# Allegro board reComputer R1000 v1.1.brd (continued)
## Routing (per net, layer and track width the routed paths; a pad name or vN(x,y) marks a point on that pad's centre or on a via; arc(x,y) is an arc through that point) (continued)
HDMI0_TX1_P1: length 11.6
  BOTTOM w0.095: L20.1 108.32,50.38 U8.7 U8.4 108.32,48.6 108.21,48.49 108.21,48 108.01,47.81 108.01,47.67 108.25,47.43 108.25,47.3 108.11,47.16 107.98,47.16 107.74,47.4 107.6,47.4 106.76,46.56 106.76,45.22 107.69,44.29 108.84,44.29 109.17,43.96 J9.4
HDMI0_TX2_N: length 72.7
  TOP w0.095: v1(59.75,37.64) 59.86,37.75 59.86,38.13 59.8,38.19 J5.172
  LYR3 w0.102: v1(59.75,56.2) 59.75,55.98 59.85,55.88 59.85,37.96 59.75,37.86 v1(59.75,37.64)
  LYR6 w0.102: v1(59.75,56.2) 59.75,55.98 59.85,55.88 59.85,55.61 60.13,55.33 61.38,55.33 61.72,54.98 100.21,54.98 103.25,51.93 104.88,51.93 105.01,51.8 105.36,51.8 105.49,51.93 105.84,51.93 105.97,51.8 106.33,51.8 106.45,51.93 106.81,51.93 106.94,51.8 107.29,51.8 107.42,51.93 107.77,51.93 107.9,51.8 108.26,51.8 108.38,51.93 108.89,51.93 109.42,51.4 109.42,51.26 109.31,51.16 v1(109.31,50.94)
HDMI0_TX2_N1: length 8.9
  BOTTOM w0.095: L19.4 109.32,50.38 U8.9 U8.2 109.32,48.53 109.43,48.42 109.43,48.17 111.28,46.32 111.28,44.91 110.18,43.81 110.18,43.38 J9.3
HDMI0_TX2_P: length 72.7
  TOP w0.095: J5.170 60.2,38.19 60.14,38.13 60.14,37.76 v1(60.26,37.64) ; 109.81,50.93 v1(109.82,50.94)
  LYR3 w0.102: v1(60.26,37.64) 60.26,37.86 60.16,37.96 60.16,55.88 60.26,55.98 v1(60.26,56.2)
  LYR6 w0.102: v1(60.26,56.2) 60.26,55.98 60.16,55.88 60.16,55.73 60.26,55.63 61.5,55.63 61.85,55.28 62.21,55.28 62.33,55.41 62.69,55.41 62.82,55.28 63.78,55.28 63.91,55.41 64.26,55.41 64.39,55.28 65.1,55.28 65.23,55.41 65.59,55.41 65.71,55.28 66.12,55.28 66.25,55.41 66.6,55.41 66.73,55.28 100.33,55.28 103.38,52.23 109.01,52.23 109.72,51.53 109.72,51.26 109.82,51.16 v1(109.82,50.94)
HDMI0_TX2_P1: length 10.8
  BOTTOM w0.095: J9.1 110.46,43.38 110.46,43.7 110.88,44.11 111.01,44.11 111.18,43.94 111.32,43.94 111.45,44.07 111.45,44.21 111.28,44.38 111.28,44.51 111.56,44.79 111.56,44.94 111.65,45.04 111.9,45.04 111.99,45.13 111.99,45.32 111.9,45.42 111.65,45.42 111.56,45.51 111.56,45.71 111.65,45.8 111.9,45.8 111.99,45.9 111.99,46.09 111.9,46.18 111.65,46.18 111.56,46.28 111.56,46.43 109.71,48.29 109.71,48.43 109.82,48.54 U8.1 U8.10 109.82,50.38 L19.1
IO_BUZZER_EN: length 6.9
  TOP w0.121: v1(27.64,72.76) 28.15,73.27 29.44,73.27 29.68,73.03 U12.15
  LYR6 w0.121: v1(25.1,72.66) 25.35,72.91 27.49,72.91 v1(27.64,72.76)
  BOTTOM w0.121: R39.1 24.62,73.14 v1(25.1,72.66)
LORA_3V3: length 7.8
  TOP w0.305: v1(71.25,36.59) 71.09,36.42 C112.2
  BOTTOM w0.305: C114.2 44.22,35.34 v1(44.25,35.32) J14.52 ; v1(71.25,36.59) 71.25,35.32 J14.2 ; J14.24 v1(59.24,34.03)
  vias: v1(41.76,26.68) v1(41.76,26.2) v1(42.19,26.71) v1(42.19,26.22) v1(50.75,24.12) v1(50.75,23.66) v1(51.21,24.12) v1(51.21,23.66) v1(59.36,33.59)
LORAWAN_SX1262_CS: length 74.4
  TOP w0.121: U12.1 28.18,67.15 v1(28.17,67.14)
  LYR3 w0.121: v1(57.84,29.12) 57.84,32.35 57.56,32.63 57,32.63 56.54,33.08 56.09,33.08 55.76,33.41 55.76,36.83 56.61,37.69 56.61,51.64 58.5,53.53 58.5,60.34 57.18,61.66 v1(57.18,66.46)
  LYR6 w0.121: v1(57.18,66.46) 56.76,66.87 55.51,66.87 54.75,67.63 43.59,67.63 43.11,67.14 v1(28.17,67.14)
  BOTTOM w0.121: J14.25 58.84,28.22 58.64,28.42 58.1,28.42 57.84,28.69 v1(57.84,29.12)
LORAWAN_SX1262_RST: length 74.5
  TOP w0.121: U12.2 28.68,66.97 27.61,65.9 v1(27.61,61.91)
  LYR3 w0.121: v1(68.2,59.91) 68.23,59.91 68.35,59.78 68.35,40.83 68.58,40.6 68.58,37.03 v1(68.04,36.49)
  LYR6 w0.121: v1(68.2,59.91) 68.13,59.98 66.91,59.98 64.49,62.39 45.27,62.39 44.2,61.33 28.2,61.33 v1(27.61,61.91)
  BOTTOM w0.121: J14.10 v1(68.04,36.49)
LORAWAN_SX1302_RST: length 78.2
  TOP w0.121: v1(62.61,36.71) 60.61,34.71 60.61,33.67 59.99,33.05 R110.2 ; v1(28.04,62.52) 28.04,65.97 29.18,67.1 U12.3
  LYR3 w0.121: v1(62.61,36.71) 62.94,36.71 65.51,39.28 65.51,52.87 65.05,53.33 65.05,53.83 65.48,54.27 v1(65.48,63.41)
  LYR6 w0.121: v1(28.04,62.52) 28.19,62.38 31.49,62.38 31.96,61.91 43.94,61.91 45.01,62.98 62.99,62.98 63.43,63.41 v1(65.48,63.41)
LTE_RESET: length 94
  TOP w0.121: v1(28.35,61.94) 28.5,62.09 28.5,65.96 29.68,67.14 U12.4
  LYR3 w0.121: v1(94.39,39.91) 94.57,40.09 94.57,42.07 89.82,46.82 v1(89.82,60.51)
  LYR6 w0.121: v1(28.35,61.94) 31.27,61.94 31.54,61.66 44.1,61.66 45.17,62.73 64.56,62.73 66.98,60.31 70.11,60.31 70.56,59.85 74.2,59.85 74.93,60.59 89.74,60.59 v1(89.82,60.51)
  BOTTOM w0.121: R109.2 v1(94.39,39.91)
NEXTRST: length 43.2
  TOP w0.121: v1(60.86,36.66) 59.79,35.6 58.47,35.6 58.24,35.37 R46.1 ; J4.100 v1(54.2,72.08)
  LYR3 w0.121: v1(60.86,36.66) 60.86,43.24 61.78,44.16 61.78,58.69 58.55,61.91 58.55,66.38 54.2,70.73 v1(54.2,72.08)
NLNKA_LED: length 24.8
  TOP w0.121: R83.1 v1(44.1,23.51) ; U4.21 52.34,37.41 50.9,38.85 46.08,38.85 45.37,38.14 45.37,36.87 v1(45.65,36.59)
  LYR3 w0.121: v1(44.1,23.51) 44.1,25.36 46.08,27.34 46.08,35.88 45.65,36.31 v1(45.65,36.59)
NPIBOOT: length 95.2
  TOP w0.121: J4.93 55.4,74.79 54.99,74.38 50.01,74.38 45.79,70.15 39.77,70.15 v1(38.81,71.11)
  LYR3 w0.121: v1(22.58,75.86) 21.49,74.76 21.49,50.86 13.52,42.89 8.11,42.89 6.71,41.49 6.71,34.61 6.07,33.97 3.02,33.97 J6.2
  LYR6 w0.121: v1(38.81,71.11) 34.06,75.86 29.09,75.86 28.43,75.2 23.24,75.2 v1(22.58,75.86)
NPWR_LED: length 122.3
  TOP w0.121: J4.95 55,74.83 54.83,74.65 49.94,74.65 45.68,70.4 40.31,70.4 v1(39.45,71.26) ; J25.1 10.65,4.82 11.41,5.57 v1(12.42,5.57)
  LYR3 w0.121: v1(12.42,5.57) 12.42,10.39 7.99,14.83 7.99,21.4 6.36,23.03 6.36,26.5 7.71,27.85 7.71,37.66 9.04,38.99 11.93,38.99 12.25,39.31 12.25,40.19 23.27,51.22 23.27,59.3 23.75,59.78 23.75,63.36 23.24,63.87 23.24,68.92 22.91,69.25 22.91,75.25 v1(23.5,75.83)
  LYR6 w0.121: v1(23.5,75.83) 23.88,75.45 28.32,75.45 28.98,76.11 34.44,76.11 39.3,71.26 v1(39.45,71.26)
NSPD_LED: length 22.8
  TOP w0.121: R84.1 v1(45.14,23.5) ; v1(46.23,36.49) 46.23,38.19 46.61,38.57 50.78,38.57 51.84,37.51 U4.22
  LYR3 w0.121: v1(45.14,23.5) 45.08,23.56 45.08,25.99 46.33,27.23 46.33,36.39 v1(46.23,36.49)
PCIE_CLK_N: length 89.8
  TOP w0.095: v1(77.97,56.84) 77.75,56.84 77.64,56.73 77.27,56.73 76.58,56.04 76.58,40.95 75.34,39.7 72.12,39.7 71.86,39.44 71.86,39.09 71.8,39.03 J5.112
  LYR6 w0.102: v1(77.97,56.84) 77.75,56.84 77.65,56.74 66.06,56.74 63.02,59.78 46.59,59.78 45.39,58.58 31.07,58.58 29.32,56.84 16.01,56.84 15.91,56.94 v1(15.69,56.94)
  BOTTOM w0.095: J62.53 14.6,56.94 14.71,56.83 15.36,56.83 15.47,56.94 v1(15.69,56.94)
PCIE_CLK_NREQ: length 90.6
  TOP w0.121: J5.102 75.83,38.75 77.83,40.75 77.83,54.6 78.84,55.61 v1(78.84,64.68)
  BOTTOM w0.121: v1(78.84,64.68) 78.39,64.68 77.57,65.5 59.97,65.5 57.73,63.26 41.22,63.26 36.27,58.31 32.57,58.31 32.04,57.78 23.4,57.78 22.8,57.19 J62.52
PCIE_CLK_P: length 89.7
  TOP w0.095: J5.110 72.2,39.03 72.14,39.09 72.14,39.33 72.24,39.42 73.97,39.42 74.09,39.29 74.45,39.29 74.58,39.42 75.45,39.42 76.86,40.83 76.86,41.19 76.99,41.31 76.99,41.67 76.86,41.79 76.86,54 76.99,54.13 76.99,54.48 76.86,54.61 76.86,54.96 76.99,55.09 76.99,55.45 76.86,55.57 76.86,55.93 77.39,56.45 77.64,56.45 77.75,56.34 v1(77.97,56.34)
  LYR6 w0.102: v1(15.69,56.43) 15.91,56.43 16.01,56.54 29.45,56.54 31.19,58.28 45.52,58.28 46.71,59.47 62.89,59.47 65.93,56.44 77.65,56.44 77.75,56.34 v1(77.97,56.34)
  BOTTOM w0.095: J62.55 14.6,56.44 14.71,56.55 15.36,56.55 15.47,56.43 v1(15.69,56.43)
PCIE_NRST: length 77.5
  TOP w0.121: J5.109 72.2,58.32 69.8,60.72 69.8,65.54 v1(70.16,65.9)
  BOTTOM w0.121: v1(70.16,65.9) 69.73,65.9 69.7,65.87 60,65.87 57.66,63.54 41.15,63.54 36.17,58.56 32.46,58.56 31.93,58.03 22.99,58.03 22.65,57.69 J62.50
PCIE_RX_N: length 89.9
  TOP w0.095: J5.118 70.6,39.03 70.66,39.09 70.66,39.64 71.44,40.41 74.42,40.41 75.54,41.53 75.54,58.87 75.86,59.19 76.23,59.19 76.34,59.31 v1(76.56,59.31)
  LYR6 w0.102: v1(15.56,59.94) 15.78,59.94 15.88,59.84 28.97,59.84 29.64,60.51 44.5,60.51 45.72,61.73 64.11,61.73 66.64,59.21 76.24,59.21 76.34,59.31 v1(76.56,59.31)
  BOTTOM w0.095: v1(15.56,59.94) 15.35,59.94 15.23,59.83 14.71,59.83 14.6,59.94 J62.41
PCIE_RX_P: length 89.9
  TOP w0.095: v1(76.56,58.8) 76.34,58.8 76.23,58.91 75.98,58.91 75.82,58.76 75.82,58.4 75.95,58.28 75.95,57.92 75.82,57.79 75.82,57.44 75.95,57.31 75.95,56.96 75.82,56.83 75.82,44.23 75.95,44.11 75.95,43.75 75.82,43.62 75.82,41.41 75.22,40.82 75.22,40.64 74.97,40.38 74.79,40.38 74.54,40.13 71.55,40.13 70.94,39.52 70.94,39.09 71,39.03 J5.116
  LYR6 w0.102: v1(76.56,58.8) 76.34,58.8 76.24,58.9 66.51,58.9 63.99,61.43 45.85,61.43 44.63,60.21 29.77,60.21 29.1,59.54 15.88,59.54 15.78,59.43 v1(15.56,59.43)
  BOTTOM w0.095: J62.43 14.6,59.44 14.71,59.55 15.23,59.55 15.35,59.43 v1(15.56,59.43)
PCIE_TX_N: length 88.6
  TOP w0.095: v1(74.56,58.43) 74.56,58.21 74.68,58.1 74.68,44.46 74.55,44.33 74.55,43.98 74.68,43.85 74.68,43.5 74.55,43.37 74.55,43.01 74.68,42.89 74.68,41.89 73.94,41.15 70.4,41.15 69.46,40.21 69.46,39.09 69.4,39.03 J5.124
  LYR6 w0.102: v1(16.59,58.44) 16.81,58.44 16.91,58.34 29.04,58.34 30.36,59.65 45.06,59.65 46.15,60.74 63.43,60.74 66.42,57.75 70.56,57.75 70.69,57.87 71.05,57.87 71.17,57.75 71.53,57.75 71.66,57.87 72.01,57.87 72.14,57.75 72.49,57.75 72.62,57.87 72.98,57.87 73.1,57.75 73.46,57.75 73.59,57.87 73.94,57.87 74.07,57.75 74.54,57.75 74.67,57.87 74.67,58.11 74.56,58.21 v1(74.56,58.43)
  BOTTOM w0.095: J62.47 14.6,58.44 14.72,58.33 16.26,58.33 16.37,58.44 v1(16.59,58.44)
PCIE_TX_P: length 88.6
  TOP w0.095: J5.122 69.8,39.03 69.74,39.09 69.74,40.1 69.89,40.25 70.06,40.25 70.3,40.49 70.3,40.65 70.51,40.87 74.06,40.87 74.96,41.77 74.96,58.1 75.07,58.21 v1(75.07,58.43)
  LYR6 w0.102: v1(75.07,58.43) 75.07,58.21 74.97,58.11 74.97,57.74 74.67,57.44 66.3,57.44 63.3,60.44 46.28,60.44 45.19,59.35 30.48,59.35 29.17,58.03 16.91,58.03 16.81,57.93 v1(16.59,57.93)
  BOTTOM w0.095: J62.49 14.6,57.94 14.72,58.05 16.26,58.05 16.37,57.93 v1(16.59,57.93)
PCIE_USIM_PRESE: length 102.9
  TOP w0.121: v1(4.63,45.88) 4.12,45.88 3.9,45.67 J16.K1
  LYR3 w0.121: v1(83.35,34.05) 85.22,35.92 v1(85.22,50.15)
  LYR6 w0.121: v1(4.63,45.88) 5.34,46.6 6.86,46.6 7.67,47.41 55.32,47.41 58.02,50.1 62.33,50.1 62.74,49.69 66.14,49.69 66.58,50.13 85.19,50.13 v1(85.22,50.15)
  BOTTOM w0.121: J15.44 v1(83.35,34.05) ; 4.99,45.88 R114.2 4.63,45.88 v1(4.63,45.88)
PL_NLED: length 126.3
  TOP w0.121: v1(11.56,4.76) 11.65,4.67 J25.2 ; v1(69.32,73.95) 69.8,74.43 J4.21
  LYR3 w0.121: v1(11.56,4.76) 11.56,10.56 7.5,14.62 7.5,21.2 5.86,22.83 5.86,26.71 7.21,28.05 7.21,41.28 8.31,42.39 13.72,42.39 22.71,51.37 22.71,60.06 22.84,60.18 22.84,64.45 v1(22.71,64.58)
  BOTTOM w0.121: v1(22.71,64.58) 22.72,64.57 38.8,64.57 39.9,65.66 44.83,65.66 49.02,69.86 60.84,69.86 61.45,70.47 66.5,70.47 67.92,71.89 67.92,72.73 69.14,73.95 v1(69.32,73.95)
POE_12V:
  vias: v1(35.49,44.21) v1(35.49,43.78) v1(35.47,43.33) v1(35.47,42.85) v1(35.94,44.18) v1(35.94,43.75) v1(35.93,43.31) v1(35.93,42.82) v1(38.71,43.65)
POE_IN_N:
  vias: v1(13.52,8.47) v1(13.97,8.47) v1(14.46,8.47) v1(19.97,17.66) v1(20.4,17.66) v1(20.83,17.66) v1(25.35,19.67) v1(25.35,19.21) v1(25.78,19.65) v1(25.78,19.19) v1(33.56,16.39) v1(33.56,15.89) v1(33.56,15.43) v1(33.56,14.97)
RS485_1_A: length 7.6
  TOP w0.508: v1(88.78,16.06) 88.75,16.06 R129.1 89.36,16.95 R124.2 89.89,16.22 R125.1
  BOTTOM w0.508: v1(88.78,16.06) 89.75,15.09 U24.12
RS485_1_B: length 7
  TOP w0.508: R130.1 90,12.16 R132.1 R129.2 88.48,14.74 v1(88.48,15.44)
  BOTTOM w0.508: U24.13 v1(88.48,15.44)
RS485_2_A: length 8.5
  TOP w0.508: v1(79.28,15.84) 79.28,14.91 R139.1 79.54,12.57 R133.2 81.79,14.24 R135.1
  BOTTOM w0.508: U26.12 78.79,15.35 v1(79.28,15.84)
RS485_2_B: length 7.5
  TOP w0.508: v1(76.94,15.89) 76.94,14.85 R139.2 76.33,14.25 R141.1 77.96,12.28 R140.1
  BOTTOM w0.508: U26.13 77.52,15.3 v1(76.94,15.89)
RS485_3_A: length 10.4
  TOP w0.508: R143.1 74.4,12.28 R142.2 72.82,13.12 72.27,13.68 70.85,13.68 R148.1 69.5,15.12 68.66,15.96 v1(68.07,15.96)
  BOTTOM w0.508: v1(68.07,15.96) 67.77,15.66 U27.12
RS485_3_B: length 8.9
  TOP w0.508: v1(66.68,16.09) R148.2 67.49,14.21 68.1,14.21 69.35,12.96 R149.1 70.98,12.28 R150.1
  BOTTOM w0.508: U27.13 66.5,15.91 v1(66.68,16.09)
RS485_LED1: length 90.9
  TOP w0.121: v1(15.67,3.09) 15.67,3.92 J25.6 ; U25.3 v1(36.07,62.63)
  LYR3 w0.121: v1(15.67,3.09) 12.22,3.09 11.15,4.15 11.15,10.6 7.24,14.52 7.24,21.1 5.62,22.73 5.62,26.81 6.96,28.16 6.96,41.38 8.21,42.63 13.62,42.63 22.41,51.42 22.41,60.41 22.43,60.44 v1(22.43,61.02)
  BOTTOM w0.121: v1(22.43,61.02) 22.46,61 34.47,61 36.07,62.6 v1(36.07,62.63)
RS485_LED2: length 89.1
  TOP w0.121: J25.7 16.64,3.93 v1(16.64,3.01) ; U25.6 v1(34.12,62.35)
  LYR3 w0.121: v1(16.64,3.01) 16.13,3.52 12.5,3.52 11.97,4.05 11.97,10.5 7.74,14.72 7.74,21.3 6.11,22.93 6.11,26.6 7.46,27.95 7.46,41.18 8.42,42.14 13.83,42.14 22.99,51.3 22.99,59.65 23.29,59.96 v1(23.29,61.45)
  BOTTOM w0.121: v1(34.12,62.35) 33.23,61.45 v1(23.29,61.45)
RS485_LED3: length 83
  TOP w0.121: v1(33.11,58.98) 33.47,58.62 U25.8 ; J25.8 17.65,3.01 v1(17.63,2.98)
  LYR3 w0.121: v1(17.63,2.98) 16.84,3.77 13.19,3.77 12.84,4.12 12.84,10.33 8.24,14.93 8.24,21.5 6.61,23.14 6.61,26.4 7.95,27.74 7.95,37.56 9.14,38.75 12.04,38.75 12.49,39.2 12.49,40.09 23.68,51.27 v1(23.68,58.74)
  BOTTOM w0.121: v1(23.68,58.74) 24.14,58.28 31.8,58.28 32.5,58.98 v1(33.11,58.98)
RS485_POWER_EN: length 93.3
  TOP w0.121: U12.14 30.18,73.47 v1(30.2,73.49) ; R122.1 v1(74.37,24.17)
  LYR3 w0.121: v1(30.71,67.88) 29.92,68.67 29.92,73.21 v1(30.2,73.49) ; v1(74.37,24.17) 75.14,24.93 75.14,27.65 75.75,28.26 75.75,44.44 69.65,50.53 69.65,66.1 v1(70.28,66.74)
  LYR6 w0.121: v1(70.28,66.74) 70.23,66.74 69.83,67.14 55.6,67.14 54.87,67.88 v1(30.71,67.88)
RTC_INT: length 6.5
  TOP w0.121: U16.3 v1(11.53,69.76)
  BOTTOM w0.121: v1(11.53,69.76) 10.72,70.57 10.72,73.22 R104.2 12.21,73.76 C109.1
RUN_PG: length 98.2
  TOP w0.121: v1(48.9,71.92) 49.15,71.67 55.3,71.67 55.8,72.17 J4.92
  LYR3 w0.121: v1(48.9,71.92) 48.9,71.72 43.61,66.43 43.61,53.28 34.67,44.33 34.67,31.41 39.21,26.87 39.21,24.99 39.7,24.5 39.7,22.59 38.36,21.25 v1(37.82,21.25)
  LYR6 w0.121: v1(37.82,21.25) 35.84,21.25 34.75,20.15 31.42,20.15 29.75,18.48 18.77,18.48 17.1,16.81 10.97,16.81 v1(9.83,17.94)
  BOTTOM w0.121: v1(9.83,17.94) 9.83,17.94 R36.2
SD_VDD_OVERRIDE: length 2.8
  TOP w0.121: J4.73 59.4,78.02 R26.1
TPM_RST: length 70.5
  TOP w0.121: v1(26.08,61.94) 26.08,61.92 26.62,61.38 28.48,61.38 28.86,61.76 28.86,65.72 30.18,67.04 U12.5
  LYR3 w0.121: v1(17.1,17.56) 17.1,17.59 15.01,19.67 13.06,19.67 12.58,20.15 12.58,23.26 12.97,23.66 12.97,26.07 10,29.04 10,37.09 10.41,37.5 12.67,37.5 22.3,47.13 25.33,47.13 26.08,47.89 v1(26.08,61.94)
  BOTTOM w0.121: J13.3 v1(17.1,17.56)
TRCT: length 32.9
  TOP w0.305: v1(47.52,22.1) C88.1 47.09,22.11 R82.2
  BOTTOM w0.305: 50.08,5.79 48.56,4.27 J10.9 ; 50.08,5.79 50.45,5.79 ; 50.08,5.79 50.27,5.98 ; 50.27,5.98 J10.5 49,16.79 J10.4 49,21.43 48.32,22.1 v1(47.52,22.1) ; 50.27,5.98 50.45,5.79 ; 50.45,5.79 J10.12
UART2_RXD: length 101.5
  TOP w0.121: R126.2 v1(77.41,18.61) ; v1(37.42,62.6) 37.37,62.64 U25.1
  LYR3 w0.121: v1(74.93,63.36) 74.2,62.63 74.2,48.1 78.08,44.22 78.08,19.29 v1(77.41,18.61)
  LYR6 w0.121: v1(37.42,62.6) 37.61,62.41 43.65,62.41 44.72,63.47 62.63,63.47 63.23,64.07 74.22,64.07 v1(74.93,63.36) ; v1(86.67,22.77) 86.72,22.72 86.72,19.87 85.46,18.61 v1(77.41,18.61)
  BOTTOM w0.121: v1(86.67,22.77) 86.67,22.9 87.21,23.44 U24.3
UART2_TXD: length 109.2
  TOP w0.121: R128.2 v1(74.51,18.61) ; U25.2 36.72,62.38 v1(36.76,62.34)
  LYR3 w0.121: v1(73.79,63.41) 73.79,63.36 73.92,63.23 73.92,47.89 77.81,44 77.81,20.47 77.35,20 75.29,20 74.51,19.22 v1(74.51,18.61)
  LYR6 w0.121: v1(91.04,22.85) 85.96,17.77 75.36,17.77 v1(74.51,18.61) ; v1(73.79,63.41) 73.38,63.82 63.32,63.82 62.73,63.23 44.85,63.23 43.79,62.16 36.94,62.16 v1(36.76,62.34)
  BOTTOM w0.121: v1(91.04,22.85) 91.02,22.86 U24.6
UART_3V3: length 92.3
  TOP w0.254: U15.1 35.09,55.19 34.8,55.49 34.8,56.48 v1(34.72,56.55) 34.8,56.63 C100.2 ; v1(33.38,53.02) 33.64,53.28 R98.1
  LYR3 w0.381: v1(59.79,7.05) 59.34,7.5 59.34,13.52 57.61,15.25 57.61,17.49 54.82,20.28 v1(54.82,21.35) ; v1(34.72,56.55) 33.78,55.61 33.78,53.73 33.38,53.33 v1(33.38,53.02) 33.82,52.58 33.82,51.82 33.33,51.32 28.65,51.32 26.67,49.34 26.67,47.71 25.89,46.93 25.89,38.65 28.32,36.21 28.32,30.49 v1(29.12,29.69) 32.9,25.92 v1(32.9,23.79)
  LYR6 w0.381: v1(32.9,23.79) 32.94,23.74 37.67,23.74 38.51,22.9 48.57,22.9 50.06,21.4 54.76,21.4 v1(54.82,21.35)
  BOTTOM w0.381: v1(59.79,7.05) 59.92,6.92 TP21.1 ; D24.1 29.14,29.68 v1(29.12,29.69)
USB1_RST: length 65.6
  TOP w0.121: v1(76.63,68.52) 77.27,69.15 v1(77.27,72.76) ; U4.12 55.51,33.98 56.01,34.48 C55.1 56.74,34.75 56.92,34.94 57.6,34.94 58.22,34.32 R46.2 ; R46.2 58.51,34.32 58.78,34.58 58.78,35.01 59.01,35.24 60.28,35.24 61.29,36.26 v1(61.29,37.17) ; R46.2 R44.2
  LYR3 w0.121: v1(58.8,68.34) 58.8,62.19 62.05,58.94 62.05,43.9 61.19,43.04 61.19,37.27 v1(61.29,37.17)
  BOTTOM w0.121: R64.1 v1(77.27,72.76) ; v1(76.63,68.52) 58.92,68.52 58.8,68.4 v1(58.8,68.34)
USB2_RST: length 17.4
  TOP w0.121: U5.26 v1(94.87,67.95)
  BOTTOM w0.121: v1(94.87,67.95) 94.5,67.95 93.65,68.8 88.16,68.8 C61.1 R52.2 R59.2 82.4,73.1 81.89,73.61 R71.2 81.07,73.61 U6.2
USB2_RST_EN: length 57.9
  TOP w0.121: U12.13 30.96,72.56 31.12,72.4 32.36,72.4 33.05,71.72 v1(33.05,71.26)
  LYR6 w0.121: v1(81.86,72.71) 78.28,72.71 77.14,73.85 70.44,73.85 69.95,74.33 67.67,74.33 66.65,75.35 64.61,75.35 64.39,75.58 54.69,75.58 47.32,68.21 37.29,68.21 34.55,70.95 33.35,70.95 v1(33.05,71.26)
  BOTTOM w0.121: R71.1 v1(81.86,72.71)
USB2_VBUS_EN1: length 8.2
  TOP w0.121: R65.1 99.6,73.32 v1(99.49,73.21) 99.49,73.16 99.4,73.07 U5.12 ; v1(101.46,72.41) 101.6,72.27 102.57,72.27 102.81,72.52 R75.2 103.29,73.38 103.67,73.76 U7.1
  LYR6 w0.121: v1(99.49,73.21) 99.62,73.34 100.54,73.34 v1(101.46,72.41)
USB2_VBUS_EN2: length 11.5
  TOP w0.121: R66.1 97.26,73.19 v1(97.23,73.16) 97.4,73 U5.16 ; U7.4 103.68,69.95 v1(103.66,69.96) 103.65,69.95 R74.2
  LYR6 w0.121: v1(97.23,73.16) 97.28,73.16 97.89,72.55 100.69,72.55 101.22,72.02 103.33,72.02 103.66,71.69 v1(103.66,69.96)
USB2_VRCURN1: length 9.8
  TOP w0.121: U7.2 105.68,72.49 v1(105.72,72.53) ; U5.13 v1(98.9,73.2) 98.92,73.22 R60.1
  LYR6 w0.121: v1(105.72,72.53) 104.55,73.7 99.34,73.7 98.9,73.26 v1(98.9,73.2)
USB2_VRCURN2: length 14.8
  TOP w0.121: R61.1 96.59,73.22 v1(96.6,73.21) 96.9,72.91 U5.17 ; v1(105.74,71.21) 105.69,71.21 105.68,71.22 U7.3
  LYR6 w0.121: v1(105.74,71.21) 106.2,71.67 106.2,73.11 105.31,74 97.39,74 v1(96.6,73.21)
USB_0M: length 15.5
  TOP w0.114: v1(51.34,28.8) 51.45,28.69 51.45,28.43 51.34,28.32 U4.58 ; U3.7 v1(58.72,29.59)
  LYR3 w0.127: v1(58.72,29.59) 60,29.59 60.12,29.46 60.12,28.76 59.87,28.51 59.75,28.51 59.44,28.21 59.44,28.08 59.16,27.8 54.31,27.8 53.75,28.36 53.75,29.02 52.94,29.83 51.74,29.83 51.44,29.53 51.44,29.15 51.34,29.05 v1(51.34,28.8)
USB_0P: length 15.5
  TOP w0.114: U3.1 v1(61.84,29.59) ; U4.59 51.84,28.32 51.73,28.43 51.73,28.69 v1(51.84,28.8)
  LYR3 w0.127: v1(51.84,28.8) 51.84,29.05 51.74,29.15 51.74,29.4 51.87,29.53 52.81,29.53 53.44,28.89 53.44,28.23 54.18,27.49 59.29,27.49 60.43,28.64 60.43,29.46 60.56,29.59 v1(61.84,29.59)
USB_1M: length 42.8
  TOP w0.114: U3.6 v1(59.09,29.99)
  LYR3 w0.127: v1(35.97,24.25) 37.19,24.25 37.32,24.12 37.32,23.94 36.55,23.18 36.55,21.2 38.74,19.01 41.91,19.01 45.52,22.62 53.57,22.62 54.66,23.71 57.38,23.71 62.63,28.96 62.63,30.22 61.98,30.87 60.56,30.87 60.11,30.42 60.11,30.12 59.98,29.99 v1(59.09,29.99)
  BOTTOM w0.114: U14.6 v1(35.97,24.25)
USB_1P: length 42.8
  TOP w0.114: U3.2 v1(61.44,29.99)
  LYR3 w0.127: v1(61.44,29.99) 60.54,29.99 60.42,30.12 60.42,30.3 60.69,30.57 61.85,30.57 62.32,30.1 62.32,29.08 61.97,28.73 61.79,28.73 61.53,28.47 61.53,28.3 61.28,28.04 61.1,28.04 60.85,27.79 60.85,27.61 60.6,27.36 60.42,27.36 60.17,27.11 60.17,26.93 59.92,26.68 59.74,26.68 59.49,26.43 59.49,26.25 57.25,24.01 56.47,24.01 56.34,24.14 55.98,24.14 55.86,24.01 55.5,24.01 55.37,24.14 55.02,24.14 54.89,24.01 54.54,24.01 53.44,22.92 53.09,22.92 52.96,23.05 52.61,23.05 52.48,22.92 52.12,22.92 52,23.05 51.64,23.05 51.51,22.92 50.5,22.92 50.37,23.05 50.02,23.05 49.89,22.92 49.41,22.92 49.28,23.05 48.92,23.05 48.8,22.92 47.98,22.92 47.86,23.05 47.5,23.05 47.37,22.92 46.46,22.92 46.33,23.05 45.98,23.05 45.85,22.92 45.39,22.92 44.59,22.12 44.41,22.12 44.16,21.87 44.16,21.69 43.59,21.12 43.41,21.12 43.16,20.87 43.16,20.69 42.67,20.2 42.49,20.2 42.24,19.95 42.24,19.77 41.79,19.32 41.05,19.32 40.92,19.44 40.57,19.44 40.44,19.32 39.83,19.32 39.7,19.44 39.35,19.44 39.22,19.32 38.86,19.32 38.42,19.76 38.42,19.94 38.17,20.19 37.99,20.19 36.85,21.33 36.85,22.08 36.98,22.21 36.98,22.57 36.85,22.69 36.85,23.05 37.62,23.82 37.62,24.12 37.75,24.25 v1(38.97,24.25)
  BOTTOM w0.114: U14.2 v1(38.97,24.25)
USB_C_DM: length 40
  TOP w0.114: R530.2 59.24,10.18 59.24,10.35 59.62,10.73 59.62,13.45 57.08,15.99 55.11,15.99 v1(54.99,16.1)
  LYR3 w0.127: v1(54.99,16.1) 55.1,16 55.44,16 55.68,16.24 55.68,16.9 55.55,17.03 55.55,17.39 55.68,17.51 55.68,18.02 54.26,19.44 54.08,19.44 53.83,19.7 53.83,19.87 53.55,20.15 53.37,20.15 53.11,20.41 53.11,20.59 52.43,21.27 52.07,21.27 51.95,21.14 51.59,21.14 51.46,21.27 45.8,21.27 42.29,17.77 37.38,17.77 36.87,18.28 36.87,19.12 36.77,19.22 v1(36.77,19.47)
  BOTTOM w0.114: U14.5 37.06,22.77 37.32,22.52 37.32,22.15 36.88,21.72 36.88,19.8 36.77,19.69 v1(36.77,19.47)
USB_C_DP: length 40
  TOP w0.114: R531.2 58.96,10.19 58.96,10.47 59.34,10.85 59.34,11.2 59.21,11.33 59.21,11.68 59.34,11.81 59.34,12.37 59.21,12.49 59.21,12.85 59.34,12.98 59.34,13.33 57.64,15.03 57.46,15.03 57.21,15.28 57.21,15.46 56.96,15.71 56.07,15.71 55.95,15.58 55.59,15.58 55.46,15.71 55.11,15.71 v1(54.99,15.59)
  LYR3 w0.127: v1(37.28,19.47) 37.28,19.22 37.18,19.12 37.18,18.4 37.51,18.07 42.17,18.07 45.67,21.58 52.56,21.58 55.98,18.15 55.98,16.12 55.56,15.7 55.1,15.7 v1(54.99,15.59)
  BOTTOM w0.114: U14.3 37.86,22.79 37.59,22.52 37.59,22.03 37.16,21.6 37.16,19.8 37.28,19.69 v1(37.28,19.47)
USB_DET: length 22.6
  TOP w0.121: U5.27 v1(94.64,67.45)
  BOTTOM w0.121: v1(94.64,67.45) 94.44,67.45 93.55,68.34 88.01,68.34 84.51,71.84 76.96,71.84 76.57,72.24 R51.2 C60.1
USB_DM: length 24.7
  TOP w0.114: U3.5 59.88,31.31 60.12,31.56 60.12,32.35 v1(60.01,32.46) ; J5.103 73.4,42.42 73.34,42.48 73.34,43.03 73.46,43.15 v1(73.46,43.37)
  LYR3 w0.127: v1(73.46,43.37) 73.46,43.12 73.35,43.02 73.35,41.21 69.5,37.35 69.5,35.72 66.17,32.4 62.13,32.4 61.34,31.61 60.42,31.61 60.11,31.91 60.11,32.36 v1(60.01,32.46)
USB_DP: length 24.6
  TOP w0.114: U3.3 60.68,31.29 60.4,31.56 60.4,32.35 v1(60.52,32.46) ; J5.105 73,42.42 73.06,42.48 73.06,43.03 72.95,43.15 v1(72.95,43.37)
  LYR3 w0.127: v1(72.95,43.37) 72.95,43.12 73.05,43.02 73.05,41.33 72.8,41.08 72.62,41.08 72.37,40.83 72.37,40.65 72.12,40.4 71.94,40.4 71.68,40.15 71.68,39.97 71.43,39.72 71.25,39.72 71,39.47 71,39.29 70.67,38.95 70.49,38.95 70.23,38.7 70.23,38.52 69.19,37.48 69.19,35.85 68.94,35.6 68.76,35.6 68.51,35.35 68.51,35.17 66.73,33.38 66.55,33.38 66.29,33.13 66.29,32.95 66.04,32.7 65.15,32.7 65.03,32.83 64.67,32.83 64.54,32.7 64.19,32.7 64.06,32.83 63.71,32.83 63.58,32.7 62.97,32.7 62.84,32.83 62.49,32.83 62.36,32.7 62,32.7 61.22,31.91 60.54,31.91 60.42,32.04 60.42,32.36 v1(60.52,32.46)
USB_HUB1_DM2: length 83.9
  TOP w0.114: v1(55.68,28.47) 55.67,28.48 U4.1
  LYR3 w0.127: v1(53.62,65.67) 53.72,65.77 54.31,65.77 54.56,65.52 54.56,28.91 54.9,28.57 55.33,28.57 55.43,28.47 v1(55.68,28.47) ; v1(28.58,79.84) 28.9,79.53 28.9,79.02 28.76,78.88 28.76,63.72 29.04,63.44 29.48,63.44 29.58,63.33 v1(29.82,63.33)
  LYR6 w0.127: v1(53.62,65.67) 53.52,65.77 45.72,65.77 43.39,63.44 30.17,63.44 30.07,63.33 v1(29.82,63.33)
  BOTTOM w0.114: J61.6 28.65,80.4 28.63,80.38 28.63,79.89 v1(28.58,79.84)
USB_HUB1_DM3: length 78
  TOP w0.114: v1(92.64,64.19) 92.75,64.07 93.11,64.07 93.23,64.2 93.59,64.2 93.72,64.07 94.07,64.07 94.2,64.2 94.55,64.2 94.68,64.07 95.04,64.07 95.16,64.2 95.52,64.2 95.65,64.07 96.05,64.07 96.18,64.2 96.48,64.2 96.61,64.07 96.91,64.07 97.51,64.67 97.51,65.85 97.4,65.96 U5.30 ; v1(58.99,31.19) 58.88,31.08 58.88,30.55 57.91,29.59 55.69,29.59 55.58,29.48 U4.3
  LYR3 w0.127: v1(67.49,63.36) 67.49,63.11 67.39,63.01 67.39,36.89 64.49,34 62.13,34 61.06,32.93 59.82,32.93 58.89,32 58.89,31.29 v1(58.99,31.19)
  LYR6 w0.127: v1(67.49,63.36) 67.49,63.11 67.39,63.01 67.39,62.7 68.13,61.96 68.48,61.96 68.61,62.09 68.96,62.09 69.09,61.96 70.16,61.96 70.28,62.09 70.64,62.09 70.77,61.96 71.71,61.96 72.6,62.85 72.95,62.85 73.08,62.98 73.43,62.98 73.56,62.85 74.12,62.85 74.25,62.98 74.6,62.98 74.73,62.85 85.58,62.85 86.81,64.08 92.53,64.08 v1(92.64,64.19)
USB_HUB1_DP2: length 83.9
  TOP w0.114: v1(55.68,28.98) U4.2
  LYR3 w0.127: v1(53.62,66.18) 53.72,66.08 54.43,66.08 54.87,65.65 54.87,29.04 55.03,28.88 55.33,28.88 55.43,28.98 v1(55.68,28.98) ; v1(29.52,79.84) 29.2,79.53 29.2,78.89 29.06,78.75 29.06,68.11 29.19,67.98 29.19,67.63 29.06,67.5 29.06,66.92 29.19,66.79 29.19,66.43 29.06,66.31 29.06,65.95 29.19,65.82 29.19,65.47 29.06,65.34 29.06,64.99 29.19,64.86 29.19,64.5 29.06,64.38 29.06,63.85 29.17,63.74 29.48,63.74 29.58,63.84 v1(29.82,63.84)
  LYR6 w0.127: v1(29.82,63.84) 30.07,63.84 30.17,63.74 43.26,63.74 45.6,66.08 53.52,66.08 v1(53.62,66.18)
  BOTTOM w0.114: v1(29.52,79.84) 29.52,80.35 29.92,80.76 J61.4
USB_HUB1_DP3: length 78.1
  TOP w0.114: v1(92.64,63.68) 92.75,63.79 97.03,63.79 97.79,64.55 97.79,65.85 97.9,65.96 U5.31 ; v1(58.49,31.19) 58.6,31.08 58.6,30.67 58.42,30.49 58.26,30.49 58.18,30.57 58.01,30.57 57.85,30.4 57.85,30.24 57.93,30.16 57.93,30 57.8,29.87 55.69,29.87 55.58,29.98 U4.4
  LYR3 w0.127: v1(66.98,63.36) 66.98,63.11 67.08,63.01 67.08,37.02 64.37,34.3 62,34.3 60.94,33.24 59.69,33.24 58.59,32.13 58.59,31.29 v1(58.49,31.19)
  LYR6 w0.127: v1(92.64,63.68) 92.53,63.78 86.93,63.78 85.7,62.55 72.72,62.55 71.83,61.66 68,61.66 67.08,62.57 67.08,63.01 66.98,63.11 v1(66.98,63.36)
USB_HUB2_DM1: length 24.2
  TOP w0.114: v1(102.68,67.45) 102.46,67.45 102.35,67.56 102,67.56 101.89,67.45 U5.1
  LYR6 w0.127: v1(115.13,59.63) 115.23,59.73 115.98,59.73 117.05,60.79 117.05,62.34 115.85,63.54 104.68,63.54 103.99,64.22 103.99,64.99 102.19,66.79 102.19,67.42 102.31,67.55 102.58,67.55 v1(102.68,67.45)
  BOTTOM w0.114: v1(115.13,59.63) 115.11,59.63 115.1,59.62 L4.4
USB_HUB2_DM2: length 24.3
  TOP w0.114: U5.3 v1(101.93,68.45)
  LYR6 w0.127: v1(101.93,68.45) 101.69,68.45 101.59,68.55 101.35,68.55 101.22,68.42 101.22,68.07 101.35,67.94 101.35,67.59 101.22,67.46 101.22,66.1 101.35,65.98 101.35,65.62 101.22,65.49 101.22,65.01 101.47,64.76 101.65,64.76 101.9,64.51 101.9,64.33 102.16,64.08 102.34,64.08 102.59,63.83 102.59,63.65 102.84,63.4 103.02,63.4 103.27,63.14 103.27,62.97 103.52,62.71 103.7,62.71 103.95,62.46 103.95,62.28 104.2,62.03 104.38,62.03 104.64,61.78 104.64,61.6 105.14,61.1 106,61.1 106.12,61.23 106.48,61.23 106.61,61.1 106.96,61.1 107.09,61.23 107.44,61.23 107.57,61.1 107.93,61.1 108.05,61.23 108.41,61.23 108.54,61.1 108.89,61.1 109.02,61.23 109.37,61.23 109.5,61.1 109.86,61.1 109.98,61.23 110.34,61.23 110.47,61.1 110.82,61.1 110.95,61.23 111.31,61.23 111.43,61.1 111.79,61.1 111.91,61.23 112.27,61.23 112.4,61.1 112.75,61.1 112.88,61.23 113.24,61.23 113.36,61.1 114.24,61.1 114.36,61.23 114.36,61.28 114.49,61.4 114.75,61.4 114.87,61.28 114.87,61.23 115,61.1 115.34,61.1 115.65,61.4 115.65,61.84 115.52,61.96 115.27,61.96 v1(115.17,61.86)
  BOTTOM w0.114: L5.2 115.13,61.85 115.14,61.86 v1(115.17,61.86)
USB_HUB2_DM3: length 112.2
  TOP w0.114: v1(102.71,69.95) 102.49,69.95 102.37,70.06 102,70.06 101.89,69.95 U5.6
  LYR3 w0.127: v1(38.37,37.31) 38.47,37.41 38.47,42.57 46.33,50.43 46.33,65.11 v1(46.23,65.21)
  LYR6 w0.127: v1(102.71,69.95) 102.46,69.95 102.36,70.05 100.77,70.05 95.89,65.16 62.87,65.16 62.13,64.43 46.64,64.43 46.33,64.73 46.33,65.11 v1(46.23,65.21)
  BOTTOM w0.114: J14.36 54.44,34.13 54.18,33.87 54.18,33.53 53.81,33.16 46.67,33.16 45.71,34.12 42.89,34.12 40.86,36.16 38.88,36.16 38.48,36.55 38.48,37.2 v1(38.37,37.31)
USB_HUB2_DM4: length 50.2
  TOP w0.114: U5.8 v1(101.93,70.95)
  LYR3 w0.127: v1(86.39,36.59) 86.39,36.83 86.29,36.93 86.29,65.71 86.39,65.81 v1(86.39,66.05)
  LYR6 w0.127: v1(86.39,66.05) 86.39,66.3 86.29,66.4 86.29,66.64 86.41,66.76 87.23,66.76 87.35,66.64 87.71,66.64 87.84,66.76 88.37,66.76 88.5,66.64 88.85,66.64 88.98,66.76 89.33,66.76 89.46,66.64 89.82,66.64 89.94,66.76 90.45,66.76 90.58,66.64 90.93,66.64 91.06,66.76 95.66,66.76 99.95,71.05 101.59,71.05 101.69,70.95 v1(101.93,70.95)
  BOTTOM w0.114: J15.36 86.55,36.47 86.43,36.59 v1(86.39,36.59)
USB_HUB2_DP1: length 24.2
  TOP w0.114: U5.2 101.89,67.95 102,67.84 102.35,67.84 102.46,67.95 v1(102.68,67.95)
  LYR6 w0.127: v1(102.68,67.95) 102.58,67.85 102.19,67.85 101.88,67.55 101.88,66.66 103.69,64.86 103.69,64.1 104.55,63.23 115.73,63.23 116.74,62.22 116.74,60.92 115.86,60.04 115.23,60.04 v1(115.13,60.14)
  BOTTOM w0.114: v1(115.13,60.14) 115.11,60.12 L4.1
USB_HUB2_DP2: length 24.5
  TOP w0.114: U5.4 101.92,68.95 v1(101.93,68.96)
  LYR6 w0.127: v1(115.17,62.37) 115.27,62.27 115.65,62.27 115.95,61.96 115.95,61.28 115.47,60.79 105.01,60.79 100.92,64.89 100.92,68.55 101.22,68.86 101.59,68.86 101.69,68.96 v1(101.93,68.96)
  BOTTOM w0.114: v1(115.17,62.37) 115.15,62.35 L5.3
USB_HUB2_DP3: length 112.1
  TOP w0.114: U5.7 101.89,70.45 102,70.34 102.37,70.34 102.49,70.45 v1(102.71,70.45)
  LYR3 w0.127: v1(38.88,37.31) 38.78,37.41 38.78,42.44 46.64,50.3 46.64,65.11 v1(46.74,65.21)
  LYR6 w0.127: v1(102.71,70.45) 102.46,70.45 102.36,70.35 100.64,70.35 95.76,65.47 62.74,65.47 62,64.73 51.72,64.73 51.59,64.86 51.23,64.86 51.11,64.73 50.75,64.73 50.62,64.86 50.27,64.86 50.14,64.73 49.56,64.73 49.43,64.86 49.08,64.86 48.95,64.73 48.29,64.73 48.16,64.86 47.81,64.86 47.68,64.73 46.76,64.73 46.64,64.86 46.64,65.11 v1(46.74,65.21)
  BOTTOM w0.114: v1(38.88,37.31) 38.76,37.2 38.76,36.66 38.99,36.44 39.35,36.44 39.47,36.56 39.83,36.56 39.96,36.44 40.97,36.44 41.22,36.18 41.4,36.18 41.66,35.93 41.66,35.75 41.91,35.5 42.09,35.5 42.34,35.25 42.34,35.07 43,34.4 45.82,34.4 46.11,34.12 46.29,34.12 46.54,33.87 46.54,33.69 46.79,33.44 47.53,33.44 47.65,33.57 48.01,33.57 48.14,33.44 48.77,33.44 48.9,33.57 49.25,33.57 49.38,33.44 49.96,33.44 50.09,33.57 50.45,33.57 50.57,33.44 51.06,33.44 51.18,33.57 51.54,33.57 51.67,33.44 52.17,33.44 52.3,33.57 52.66,33.57 52.78,33.44 53.7,33.44 53.9,33.64 53.9,33.87 53.64,34.13 J14.38
USB_HUB2_DP4: length 50.2
  TOP w0.114: v1(101.93,71.46) 101.92,71.45 U5.9
  LYR3 w0.127: v1(85.88,36.59) 85.88,36.83 85.98,36.93 85.98,65.71 85.88,65.81 v1(85.88,66.05)
  LYR6 w0.127: v1(85.88,66.05) 85.88,66.3 85.98,66.4 85.98,66.76 86.29,67.07 95.53,67.07 99.82,71.36 101.59,71.36 101.69,71.46 v1(101.93,71.46)
  BOTTOM w0.114: v1(85.88,36.59) 85.86,36.59 85.75,36.47 J15.38
USB_OTG_ID: length 86.7
  TOP w0.121: v1(74.15,42.48) 73.8,42.14 J5.101 ; v1(62.79,28.26) 62.08,28.97 U3.10
  LYR3 w0.121: v1(74.15,42.48) 74.15,37.81 64.59,28.26 v1(62.79,28.26) 61.9,27.37 v1(61.9,24.55)
  LYR6 w0.121: v1(61.9,24.55) 58.04,24.55 55.96,22.47 49.53,22.47 47.88,24.12 41,24.12 39.84,25.28 v1(38.18,25.28) 37.69,25.77 33.25,25.77 31.27,27.75 11.99,27.75 10.44,29.3 v1(10.44,30.39)
  BOTTOM w0.121: R34.2 9.98,32.11 R35.1 9.98,30.64 C37.1 v1(10.44,30.39) ; U14.10 v1(38.18,25.28)
USB_OTG_ID1: length 4.7
  BOTTOM w0.121: 4.68,32.78 J6.5 8.8,32.78 R34.1
USB_TO_UART_DM: length 35.5
  TOP w0.114: U15.8 37.64,52.48 37.53,52.37 37.53,51.48 37.77,51.24 37.93,51.24 38.01,51.32 38.18,51.32 38.34,51.16 38.34,51 38.26,50.92 38.26,50.76 38.71,50.3 39.19,50.3 v1(39.31,50.42)
  LYR3 w0.127: v1(39.31,50.42) 39.21,50.32 38.8,50.32 33.71,45.22 33.71,30.8 37.3,27.2 37.3,24.78 37.18,24.65 v1(36.3,24.65)
  BOTTOM w0.114: U14.7 v1(36.3,24.65)
USB_TO_UART_DP: length 35.5
  TOP w0.114: U15.7 37.14,52.48 37.25,52.37 37.25,51.37 38.6,50.02 39.19,50.02 v1(39.31,49.91)
  LYR3 w0.127: v1(38.61,24.65) 37.73,24.65 37.61,24.78 37.61,27.33 35.38,29.56 35.38,29.74 35.13,29.99 34.95,29.99 34.7,30.24 34.7,30.42 34.44,30.67 34.26,30.67 34.01,30.92 34.01,45.1 34.26,45.35 34.44,45.35 34.7,45.6 34.7,45.78 34.95,46.03 35.13,46.03 35.38,46.28 35.38,46.46 38.93,50.01 39.21,50.01 v1(39.31,49.91)
  BOTTOM w0.114: U14.1 v1(38.61,24.65)
USBA_GND:
  vias: v1(114.35,64.58) v1(114.81,64.6) v1(115.27,64.63)
USBC_DM: length 9.3
  TOP w0.114: J11.A7 63.85,8.71 61.83,8.71 D23.2 60.93,8.72 60.05,8.72 59.92,8.85 59.92,8.92 59.84,9 59.67,9 59.59,8.92 59.59,8.8 59.51,8.72 59.25,8.72 59.13,8.84 59.13,9.28 59.33,9.48 R530.1
  LYR3 w0.076: J11.B7 65.35,8.12 65.35,8.78 65.11,9.03 J11.A7
USBC_DP: length 7.7
  TOP w0.114: R531.1 58.85,9.39 58.85,8.72 59.13,8.44 60.74,8.44 61.18,8 D22.2 61.81,8.44 63.85,8.44 J11.A6 64.46,8.13 J11.B6
USER_LED_B: length 85.7
  TOP w0.121: U12.8 31.91,69.86 v1(31.98,69.79) ; J25.4 v1(13.65,4.79)
  LYR3 w0.121: v1(24.92,67.5) 25.38,67.04 25.38,65.01 24.89,64.52 24.89,51.05 13.51,39.67 13.51,38.75 12.51,37.74 10.23,37.74 9.7,37.22 9.7,28.99 12.72,25.97 12.72,23.76 11.12,22.16 11.12,13.17 11.63,12.66 11.64,12.66 15.14,9.16 15.14,4.63 14.89,4.38 14.06,4.38 v1(13.65,4.79)
  LYR6 w0.121: v1(24.92,67.5) 25.23,67.5 26.96,69.23 31.4,69.23 31.96,69.79 v1(31.98,69.79)
USER_LED_G: length 84.5
  TOP w0.121: v1(13.25,5.21) 12.65,4.61 J25.3 ; v1(31.85,69.13) 31.85,69.23 31.73,69.36 U12.7
  LYR3 w0.121: v1(13.25,5.21) 13.08,5.37 13.08,10.45 12.5,11.04 12.48,11.04 8.49,15.03 8.49,21.61 6.85,23.24 6.85,26.3 8.2,27.64 8.2,37.46 9.24,38.5 12.14,38.5 12.74,39.1 12.74,39.99 24.13,51.38 24.13,66.64 v1(23.8,66.97)
  LYR6 w0.121: v1(31.85,69.13) 31.69,68.96 27.04,68.96 25.05,66.97 v1(23.8,66.97)
USER_LED_R: length 81.7
  TOP w0.121: v1(31.14,66.71) 31.14,68 30.68,68.47 U12.6 ; J25.5 v1(14.65,4.78)
  LYR3 w0.121: v1(14.65,4.78) 14.84,4.96 14.84,9.11 10.87,13.07 10.87,22.26 12.47,23.86 12.47,25.87 9.45,28.89 9.45,37.32 10.12,37.99 12.4,37.99 13.26,38.85 13.26,39.77 24.64,51.15 24.64,65.01 v1(24.95,65.32)
  LYR6 w0.121: v1(31.14,66.71) 26.34,66.71 v1(24.95,65.32)
USIM_1V8: length 51.2
  LYR3 w0.508: v1(5.39,65.32) 5.39,64.17 4.47,63.26 4.47,47.79 5.92,46.34 v1(5.92,45.88)
  LYR6 w0.508: v1(33.25,68.77) 33,68.52 27.31,68.52 24.11,65.32 v1(5.39,65.32)
  BOTTOM w0.305: R114.1 v1(5.92,45.88)
  BOTTOM w0.508: TP29.1 5.94,45.86 v1(5.92,45.88)
USIM_CLK: length 106
  TOP w0.121: J16.C3 29.08,52.12 30.3,53.35 D31.2 31.66,53.14 C123.1 v1(31.27,52.54)
  LYR3 w0.121: v1(91.01,61.9) 91.08,61.83 91.08,46.53 95.19,42.42 95.19,36.5 98.28,33.41 98.86,33.41 v1(99.35,33.9)
  BOTTOM w0.121: v1(31.27,52.54) 31.27,52.74 32.57,54.05 32.57,54.58 33.89,55.89 37.14,55.89 42.91,61.66 58.62,61.66 60.81,63.84 75.03,63.84 76.05,62.83 89.23,62.83 90.16,61.9 v1(91.01,61.9) ; J15.12 v1(99.35,33.9)
USIM_DATA: length 139.5
  TOP w0.121: v1(6.2,48.12) 5.18,49.14 5.18,51.32 4.38,52.12 J16.C7
  LYR3 w0.121: v1(100.15,33.85) 100.14,33.85 99.45,33.17 98.09,33.17 94.89,36.37 94.89,42.29 90.55,46.62 90.55,62.72 v1(90.66,62.83)
  BOTTOM w0.121: v1(6.2,48.12) 6.19,48.11 D30.2 5.7,47.48 C122.1 R115.2 8.38,46.58 11.05,49.26 11.05,52.99 12.48,54.42 30.61,54.42 32.21,56.02 33.12,56.02 34.46,57.36 36.9,57.36 41.86,62.32 58.27,62.32 60.52,64.57 75.33,64.57 76.35,63.55 89.67,63.55 90.4,62.83 v1(90.66,62.83) ; J15.10 v1(100.15,33.85)
USIM_GND: length 7.6
  BOTTOM w0.305: 107.79,35.84 107.79,35.83 R108.1
  BOTTOM w0.508: 107.79,35.84 106.61,37.02 102.92,37.02 102.55,36.64 J15.4
USIM_RST: length 103.9
  TOP w0.121: v1(31.3,54.16) C128.1 31.66,54.79 D32.2 31.12,54.66 J16.C2
  LYR3 w0.121: v1(91.42,62.39) 91.42,46.67 95.53,42.56 95.53,36.64 98.24,33.93 v1(98.55,33.93)
  BOTTOM w0.121: v1(31.3,54.16) 31.3,54.28 31.98,54.95 32.6,54.95 33.78,56.13 36.21,56.13 37.07,56.99 37.07,57.01 42.02,61.96 58.32,61.96 60.63,64.27 75.21,64.27 76.23,63.26 89.26,63.26 90.12,62.39 v1(91.42,62.39) ; J15.14 v1(98.55,33.93)
USIM_VDD: length 136.5
  TOP w0.305: v1(4.6,46.6) 5.13,47.13 v1(6.28,47.13)
  TOP w0.508: J16.C1 28.72,57.2 29.19,57.67 D33.2
  LYR3 w0.508: v1(92.18,62.85) 92.18,46.6 96.01,42.76 96.01,38.06 97.34,36.74 v1(100.95,36.74)
  BOTTOM w0.305: v1(4.6,46.6) 4.61,46.58 R115.1 ; v1(6.28,47.13) 8.21,47.13 10.54,49.47 10.54,53.2 12.27,54.93 30.15,54.93 v1(31.27,56.05)
  BOTTOM w0.508: v1(92.18,62.85) 91.04,63.99 76.53,63.99 75.52,65.01 60.18,65.01 57.94,62.78 41.66,62.78 36.68,57.8 33.02,57.8 v1(31.27,56.05) ; J15.8 v1(100.95,36.74)
VETH_DVDDH: length 39.5
  TOP w0.305: R82.1 46.13,23.53 v1(46.15,23.56)
  LYR3 w0.381: v1(34.98,16.95) 42.4,16.95 v1(42.42,16.93)
  BOTTOM w0.305: J18.12 23.57,8.75 24.72,9.89 33.33,9.89 J18.10 36.12,10.4 36.12,14.21 34.52,15.81 C160.1 v1(34.98,16.95) 35.21,16.95 35.56,17.31 FB9.2
  BOTTOM w0.381: v1(46.15,23.56) 45.42,22.82 44.22,22.82 43.59,22.19 43.59,18.1 v1(42.42,16.93)
N17790331: length 42.2
  TOP w0.121: J4.31 67.8,75.75 v1(67.8,74.75) ; v1(50.12,65.29) 49.26,66.15 38.21,66.15 37.66,66.7 R25.1
  LYR3 w0.121: v1(67.8,74.75) 67.8,70.95 68.35,70.4 68.35,67.12 67.8,66.57 v1(67.8,66.31)
  BOTTOM w0.121: v1(50.12,65.29) 51.52,63.89 57.49,63.89 59.91,66.31 v1(67.8,66.31)
N17790840: length 2
  TOP w0.121: J4.89 56.2,76.31 v1(56.3,76.41)
  BOTTOM w0.121: v1(56.3,76.41) TP14.1
N17790854: length 1.9
  TOP w0.121: v1(55.63,76.42) 55.8,76.24 J4.91
  BOTTOM w0.121: TP15.1 55.63,76.87 v1(55.63,76.42)
N18106868: length 2.6
  TOP w0.121: J4.19 v1(70.2,75.1)
  BOTTOM w0.121: TP12.1 68.68,76.08 69.39,75.37 69.66,75.1 v1(70.2,75.1) 70.2,75.1
N21083178: length 4.8
  TOP w0.508: v1(10.59,78.9) 10.51,78.82 D29.1
  BOTTOM w0.508: J12.2 10.9,79.21 v1(10.59,78.9) 10.52,78.83 TP23.1
N21084468: length 2.6
  BOTTOM w0.121: C109.2 12.72,73.75 R105.2 14.26,73.39 U18.2
N21116390:
  vias: v1(92.56,19.87) v1(93.04,19.9) v1(93.5,19.9) v1(93.98,19.9) v1(94.44,19.9) v1(94.92,19.9)
N21149713: length 2.6
  BOTTOM w0.121: J14.14 66.44,36.82 65.93,37.34 TP25.1
N21149734: length 3.4
  BOTTOM w0.121: J14.16 65.64,36.06 65.18,36.53 64.34,36.53 TP26.1
N21149896: length 5.4
  BOTTOM w0.121: TP27.1 56.59,23.48 56.59,25.74 56.44,25.89 J14.31
N21149903: length 2.7
  BOTTOM w0.121: J14.33 55.64,24.78 TP28.1
N21150017: length 3.3
  BOTTOM w0.121: J14.45 50.84,26.03 50.08,25.27 R111.2
N21187983: length 3.3
  TOP w0.305: R5.1 v1(109.34,35.91) R2.2
  BOTTOM w0.305: D8.2 109.34,34.57 v1(109.34,35.91)
N21187993: length 1.1
  TOP w0.305: Q2.1 108.29,35.01 R5.2
N21188161: length 2.1
  TOP w0.305: D9.1 106.11,35.89 Q2.3
N21188625: length 27.6
  TOP w0.305: v1(104.02,36.11) 104.14,36.11 104.74,36.7 D9.2 ; v1(104.02,36.11) 103.72,36.4 R7.1 ; v1(104.02,36.11) 104.02,35.99 103.71,35.69 R3.2
  LYR3 w0.305: v1(90.16,44.68) 91.48,44.68 93.88,42.28 93.88,36.69 97.87,32.7 100.61,32.7 v1(104.02,36.11)
  BOTTOM w0.305: Q1.4 90.11,44.63 v1(90.16,44.68) C1.2
N21206327: length 6.5
  TOP w0.121: X3.2 5.74,69.28 C103.1 6.7,70.27 7.36,70.93 R101.2 7.43,70.99 8.03,71.59 9.27,71.59 9.98,72.3 U16.1
N21206924: length 5.2
  TOP w0.121: U16.2 9.58,71.03 9.38,71.23 8.24,71.23 R101.1 7.94,70.28 C102.2 7.98,70.02 8.79,69.21 X3.1
N21339151: length 1.8
  TOP w0.121: R110.1 v1(59.95,33.99)
  BOTTOM w0.121: v1(59.95,33.99) 60.04,34.08 J14.22
N21339355: length 4.4
  BOTTOM w0.121: R109.1 92.15,36.59 J15.22
N21411770: length 6.8
  TOP w0.305: D34.2 65.59,17.43 v1(65.46,17.56) R118.2
  BOTTOM w0.305: v1(65.46,17.56) 63.45,19.57 TP33.1
N21419586: length 20.3
  TOP w0.121: R131.1 R127.2 v1(76.28,18.2)
  LYR6 w0.121: v1(89.75,22.85) 89.75,22.07 85.88,18.2 v1(76.28,18.2)
  BOTTOM w0.121: U24.5 v1(89.75,22.85) 88.67,22.85 88.48,23.04 U24.4
N21664516: length 1
  TOP w0.121: U3.8 59.88,28.02 R37.1
N21891930: length 3.8
  TOP w0.121: R49.1 53.02,26.27 53.32,25.97 53.87,25.97 54.2,26.29 R47.1 54.31,26.2 54.31,25.72 C56.1 54.18,24.52 X1.1
N21894342: length 6.4
  TOP w0.121: X1.3 52.26,22.38 53.34,23.46 53.34,24.8 53.01,25.14 C57.1 53.01,25.8 52.51,26.3 R49.2 52.34,26.5 U4.60
N22026897: length 27.4
  LYR3 w0.102: J18.1 25.58,12.63 25.58,12.33 25.76,12.11 26.08,12.06 26.67,12.48 26.67,13.55 22.79,17.44 22.79,21.37 23.4,21.98 23.4,23.76 23.02,24.14 20.73,24.14 19.99,24.88 15.22,24.88 14.79,25.31 14.79,26 13.92,26.86 v1(13.92,27.02)
  BOTTOM w0.095: T1.24 v1(13.92,27.02)
N22026906: length 27.4
  LYR3 w0.102: J18.2 26.99,11.1 26.5,11.78 26.54,12.01 26.91,12.27 26.98,12.34 26.98,13.68 23.09,17.56 23.09,21.25 23.7,21.86 23.7,23.89 23.14,24.45 20.86,24.45 20.12,25.18 15.34,25.18 15.09,25.44 15.09,26 15.92,26.83 v1(15.92,26.99)
  BOTTOM w0.095: T1.22 v1(15.92,26.99)
N22026915: length 26.2
  BOTTOM w0.095: J18.3 28.23,12.77 27.99,12.53 27.99,12.1 28.25,11.84 28.53,11.84 29.24,12.01 29.62,12.48 29.62,13.94 27.29,16.27 22.98,16.27 18.62,20.62 18.62,24.56 17.76,25.42 17.76,26.05 16.92,26.88 T1.21
N22026957: length 22.6
  BOTTOM w0.095: T1.15 22.92,26.95 23.78,26.1 23.78,25.75 32.06,17.47 32.06,15.19 33.24,14.01 33.96,14.01 34.42,13.55 34.42,12.58 34.08,12.24 33.88,12.09 33.38,12.17 33.25,12.35 33.25,12.68 J18.7
N22026966: length 22.7
  BOTTOM w0.095: T1.13 24.92,26.99 24.06,26.12 24.06,25.87 32.34,17.59 32.34,15.3 33.35,14.29 34.08,14.29 34.7,13.67 34.7,12.46 34.26,12.02 34.13,11.93 34.11,11.8 34.61,11.1 J18.8
N22027038: length 1.4
  BOTTOM w0.584: v1(23.92,26.66) v1(23.92,27.1) T1.14
  vias: v1(21.67,19.65) v1(21.67,19.16) v1(21.97,23.68) v1(22.43,23.68)
N22027110: length 1.4
  BOTTOM w0.584: v1(17.92,26.66) v1(17.92,27.1) T1.20
  vias: v1(8.97,19.62) v1(9.53,19.65) v1(17.07,23.46) v1(17.63,23.46)
N22027117: length 1.4
  BOTTOM w0.584: v1(20.92,26.66) v1(20.92,27.1) T1.17
  vias: v1(17.96,19.65) v1(17.99,19.09) v1(20.4,23.41) v1(20.93,23.41)
N22027433: length 19.9
  BOTTOM w0.121: J18.11 27,7.61 35.13,7.61 35.77,8.24 35.77,9.49 36.48,10.2 36.48,14.39 36.83,14.74 36.83,17 R155.2
N22027462: length 8.8
  BOTTOM w0.121: R160.2 37.16,16.34 37.16,14.64 36.76,14.24 J18.9
N22028382: length 1.4
  BOTTOM w0.584: v1(14.92,26.66) v1(14.92,27.1) T1.23
  vias: v1(11.76,19.62) v1(12.19,19.62) v1(13.95,23.46) v1(14.43,23.46)
N22029929:
  vias: v1(27.89,19.93) v1(27.89,19.49) v1(28.32,19.93) v1(28.32,19.49)
N22030276: length 1.9
  TOP w1.27: D51.4 9.42,17 R151.1
N22030277: length 1.9
  TOP w1.27: D51.3 11.82,16.97 R152.1
N22038029: length 1.4
  TOP w0.889: R156.2 C154.1
N22038032:
  vias: v1(13.11,20.59) v1(13.57,20.56) v1(14.05,20.56) v1(14.48,20.56) v1(16.79,21.45) v1(16.79,21.02) v1(20.09,21.47) v1(20.09,21.04)
N22038068: length 1.4
  TOP w0.889: C155.1 R157.2
N22038120: length 1.4
  TOP w0.889: C156.1 R158.2
N22038172: length 1.5
  BOTTOM w0.889: R159.2 23.32,22.69 C157.1
N22078660: length 26.2
  BOTTOM w0.095: T1.19 18.92,26.93 18.04,26.05 18.04,25.54 18.9,24.68 18.9,20.74 23.09,16.55 27.41,16.55 29.9,14.06 29.9,12.27 30.38,11.89 32.07,11.1 J18.6
N22078676: length 24
  LYR3 w0.102: J18.5 30.94,12.63 30.94,12.32 30.75,12.1 30.36,12.03 30.17,12.17 30.05,12.26 29.7,12.62 29.7,13.7 27.84,15.56 26.52,15.56 24.36,17.72 24.36,20.87 25,21.5 25,24.09 23.4,25.69 21.24,25.69 21.14,25.79 21.14,26.02 21.92,26.81 v1(21.92,26.99)
  BOTTOM w0.095: T1.16 v1(21.92,26.99)
N22078685: length 24
  LYR3 w0.102: J18.4 29.53,11.1 30.02,11.78 29.99,11.92 29.99,11.93 29.86,12.02 29.39,12.49 29.39,13.58 27.71,15.25 26.39,15.25 24.06,17.59 24.06,20.99 24.69,21.63 24.69,23.96 23.27,25.39 21.11,25.39 20.83,25.67 20.83,26 19.92,26.91 v1(19.92,27.02)
  BOTTOM w0.095: T1.18 v1(19.92,27.02)
N22567639: length 3.3
  TOP w0.508: v1(23.92,38.19) 25.18,39.44 v1(25.18,39.44)
  BOTTOM w0.508: T1.11 v1(23.92,38.19) ; C153.1 v1(25.18,39.44)
N22567644: length 2.8
  TOP w0.508: v1(20.74,39.49) 20.74,38.36 v1(20.9,38.21)
  BOTTOM w0.508: v1(20.9,38.21) 20.92,38.19 T1.8 ; C152.1 v1(20.74,39.49)
N22567654: length 3.1
  TOP w0.508: v1(17.92,38.19) 19.04,39.31 v1(19.04,39.42)
  BOTTOM w0.508: C151.1 v1(19.04,39.42) ; T1.5 v1(17.92,38.19)
N22567659: length 3.2
  TOP w0.508: v1(14.84,38.24) 14.84,38.32 13.93,39.23 v1(13.93,39.42)
  BOTTOM w0.508: T1.2 14.92,38.13 14.84,38.21 v1(14.84,38.24) ; C150.1 v1(13.93,39.42)
N22666345: length 2.3
  TOP w0.121: R122.2 R119.1 73.51,22.87 73.71,22.68 U23.4
N22666568: length 1.8
  TOP w0.121: R120.1 73.94,18.45 73.71,18.69 U23.3
N22695835: length 2.8
  BOTTOM w0.121: TP24.1 68.36,37.36 68.84,36.87 J14.8
N22714565: length 2.6
  BOTTOM w0.121: R103.1 R102.2 60.63,79.26 61.48,80.11 U17.7
N23370571: length 1.8
  TOP w0.121: R41.2 56.48,33.3 56.3,33.48 U4.11
N23400557: length 2.1
  TOP w0.121: R42.2 54.17,27.09 53.99,27.09 53.84,27.24 U4.63
N23401903: length 1.3
  TOP w0.254: R43.2 44.93,31.98 U4.41
N23402124: length 1.8
  TOP w0.121: R45.2 47.34,26.33 U4.50
N23405519: length 1.8
  TOP w0.121: U4.61 52.84,27.12 53.65,26.32 R47.2
N23430020: length 3.7
  TOP w0.121: v1(75.06,22.62) 74.88,22.44 R134.2
  BOTTOM w0.121: v1(75.06,22.62) 75.97,22.62 76.25,22.9 U26.3
N23430038: length 6.8
  TOP w0.121: v1(76.28,22.06) R136.2 R138.1
  BOTTOM w0.121: U26.5 78.79,23.05 78.59,22.85 77.62,22.85 ; 77.52,22.95 77.62,22.85 ; 77.52,22.95 U26.4 ; 77.52,22.95 77.52,22.85 ; 77.62,22.85 77.52,22.74 ; 77.62,22.85 77.52,22.85 ; 77.52,22.74 77.52,22.54 77.04,22.06 v1(76.28,22.06) ; 77.52,22.74 77.52,22.85
N23430129: length 4.8
  TOP w0.121: R137.2 77.01,21.42 v1(77.32,21.73)
  BOTTOM w0.121: v1(77.32,21.73) 78.01,22.41 79.71,22.41 80.06,22.77 U26.6
N23431044: length 1.7
  TOP w0.121: v1(65.2,22.92) 65.03,23.1 R144.2
  BOTTOM w0.121: v1(65.2,22.92) 65.23,22.95 U27.3
N23431062: length 4.5
  TOP w0.121: R147.1 R145.2 v1(66.55,22.95)
  BOTTOM w0.121: U27.5 67.77,23.05 67.67,22.95 66.55,22.95 v1(66.55,22.95) 66.55,23.9 U27.4
N23431153: length 3.2
  TOP w0.121: R146.2 67.41,23.2 67.77,22.85 v1(69.07,22.85)
  BOTTOM w0.121: v1(69.07,22.85) 69.04,22.87 U27.6
N23449459: length 3.9
  TOP w0.121: R94.1 66.55,7.21 64.72,7.21 64.71,7.23 J11.A5
N23449477: length 2.8
  TOP w0.121: R95.1 65.1,9.29 J11.B5
N23449775: length 3.6
  BOTTOM w0.203: C98.1 37.46,26.17 U14.9
  BOTTOM w0.305: D25.2 37.52,27.01 C98.1
  BOTTOM w0.381: D25.2 D24.2
N23449933: length 5.2
  TOP w0.121: U15.5 36.14,51.63 D26.1 34.15,52.26 R99.1 R98.2
N23449979: length 1.5
  TOP w0.254: C101.2 36.64,51.47 U15.6
N23450082: length 1.4
  TOP w0.121: R100.1 34.53,53.69 U15.4
N23450096: length 1.1
  BOTTOM w0.121: U14.8 37.06,25.85 R97.1
N23451512: length 1.6
  TOP w0.121: R53.2 96.4,65.73 U5.28
N23451530: length 11.1
  TOP w0.121: U5.22 v1(93.75,69.95)
  BOTTOM w0.121: v1(93.75,69.95) 88.76,69.95 85.89,72.82 R54.2
N23451550: length 12.2
  TOP w0.121: U5.24 v1(94.87,68.95)
  BOTTOM w0.121: R55.2 85.23,72.8 88.52,69.51 94.32,69.51 v1(94.87,68.95)
N23451563: length 12.9
  TOP w0.121: U5.25 v1(94.64,68.45)
  BOTTOM w0.121: v1(94.64,68.45) 94.64,68.49 93.96,69.18 88.48,69.18 R56.2
N23451623: length 1.4
  TOP w0.121: U5.11 99.9,73.16 R57.1
N23451671: length 2
  TOP w0.121: v1(100,65.87) 100,65.92 99.9,66.03 U5.35
  BOTTOM w0.121: v1(100,65.87) 100.1,65.98 100.1,66.99 R58.1
N23451839: length 3
  TOP w0.305: U5.34 v1(99.4,65.91)
  BOTTOM w0.305: v1(99.4,65.91) 99.32,65.99 C70.2 98.66,67.25 C69.2
N23451845: length 2.6
  TOP w0.121: U5.19 95.27,71.45 95.05,71.67 95.05,73.35 R62.1
N23451875: length 2.8
  TOP w0.305: U5.14 v1(98.4,72.96)
  BOTTOM w0.305: v1(98.4,72.96) 98.66,72.7 C72.2 98.02,71.89 C71.2
N23451879: length 10.4
  TOP w0.121: U5.21 v1(94.34,70.45)
  BOTTOM w0.121: v1(94.34,70.45) 88.72,70.45 86.58,72.59 R63.1
N23451944: length 1.5
  TOP w0.121: R69.2 98.4,65.41 U5.32
N23451981: length 1.5
  TOP w0.121: U5.18 96.4,72.86 95.91,73.35 R67.1
N23452005: length 5.5
  TOP w0.121: U5.33 98.85,66.55 R70.2 99.13,65.47 100.78,65.47 C75.1 101.2,63.98 X2.3
N23452009: length 3.4
  TOP w0.121: R68.1 94.59,71.31 94.95,70.95 U5.20
N23452027: length 6.8
  TOP w0.121: X2.1 102.76,61.55 101.73,62.57 100.21,62.57 99.73,63.05 C74.1 99.26,64.05 98.85,64.46 R70.1 R69.1
N23452966: length 7.6
  BOTTOM w0.114: L5.1 114.08,61.96 112.85,61.96 112.42,61.53 D18.2 112.38,61.52 111.93,61.97 110.63,61.97 109.55,60.9 108.33,60.9 108.22,60.78 J8.B2
N23452985: length 7.6
  BOTTOM w0.114: L5.4 114.08,62.24 112.85,62.24 112.42,62.68 D19.2 112.4,62.7 111.95,62.25 110.51,62.25 109.44,61.17 108.33,61.17 108.22,61.29 J8.B3
N23455465: length 7.3
  BOTTOM w0.121: SW1.2 5.38,17.7 D12.2 9.07,17.7 9.74,17.02 R36.1
N23456906: length 1.4
  BOTTOM w0.121: R64.2 77.95,73.73 U6.3
N23459666: length 3
  TOP w0.121: v1(46.87,37.52) 46.97,37.41 48.62,37.41 48.84,37.19 U4.28
  BOTTOM w0.121: R50.1 46.75,37.4 v1(46.87,37.52) 46.86,37.53
N23461225: length 1.3
  TOP w0.121: U4.44 44.88,30.48 R48.1
N23461314: length 2.7
  TOP w0.121: v1(45.57,29.98) 45.58,29.98 U4.45
  BOTTOM w0.121: TP19.1 44.63,30.28 44.67,30.32 45.23,30.32 v1(45.57,29.98)
N23463209: length 20.6
  TOP w0.121: J10.10 45.89,5.79 47.37,7.28 47.37,12.58 46.63,13.33 44.45,13.33 43.81,13.97 43.33,14.45 43.33,17.2 44.48,18.35 44.48,21.74 R83.2
N23463212: length 23.9
  TOP w0.121: J10.11 47.63,10.06 47.63,12.81 46.87,13.58 44.55,13.58 43.58,14.55 43.58,16.99 44.81,18.22 44.81,21.8 R84.2
N23463479: length 13.6
  TOP w0.121: U4.20 52.84,37.47 51.22,39.1 45.85,39.1 44.34,37.59 43.33,37.59 v1(42.47,36.73)
  BOTTOM w0.121: v1(42.47,36.73) TP18.1
N23466024: length 2.5
  TOP w0.121: R85.2 27.39,72.35 28.04,72.35 28.18,72.49 U12.18
N23466034: length 1.2
  TOP w0.121: R90.2 26.77,70.06 27.06,70.36 U12.22
N23466170: length 1.3
  TOP w0.121: R92.1 26.54,69.32 27.07,69.86 U12.23
N23466179: length 1.5
  TOP w0.121: U12.24 27.18,69.36 R93.1
N23473877: length 5.5
  TOP w0.508: B1.1 v1(20.32,79.92)
  BOTTOM w0.508: v1(20.32,79.92) 20.32,79.74 19.13,78.55 D13.2 18.02,78.4 R38.2
N23473909: length 4.7
  TOP w0.508: B1.2 20.32,74.38 v1(19.97,74.74)
  BOTTOM w0.508: D13.1 19.13,75.58 v1(19.97,74.74) 19.96,74.73 Q3.3
N23473945: length 2.5
  BOTTOM w0.121: Q3.1 23.18,73.65 R40.1 R39.2
N23500588: length 6.4
  BOTTOM w0.121: J62.68 22.04,53.19 22.35,52.87 22.35,49.34 21.23,48.22 OSC1.3
N23502047: length 14
  LYR3 w0.121: v1(25.33,57.39) 25.33,48.88 v1(25.69,48.51)
  BOTTOM w0.121: J62.54 23.2,56.69 23.9,57.39 v1(25.33,57.39) ; R175.2 v1(25.69,48.51)
N23514160: length 6.2
  TOP w0.121: v1(65.76,77.76) 65.38,78.14 R22.2 ; J4.46 v1(65,74.13)
  LYR3 w0.121: v1(65.76,77.76) 65.76,75.35 65,74.59 v1(65,74.13)
N23514205: length 2.7
  TOP w0.121: R23.1 64.6,78.39 J4.47
N23529653: length 23.9
  TOP w0.121: J4.80 58.2,71.39 54.84,68.03 48.39,68.03 47.37,67.02 38.13,67.02 R27.2
N23529656: length 23.4
  TOP w0.121: J4.82 57.8,71.58 54.52,68.3 48.19,68.3 47.21,67.32 38.61,67.32 37.64,68.3 R28.2
